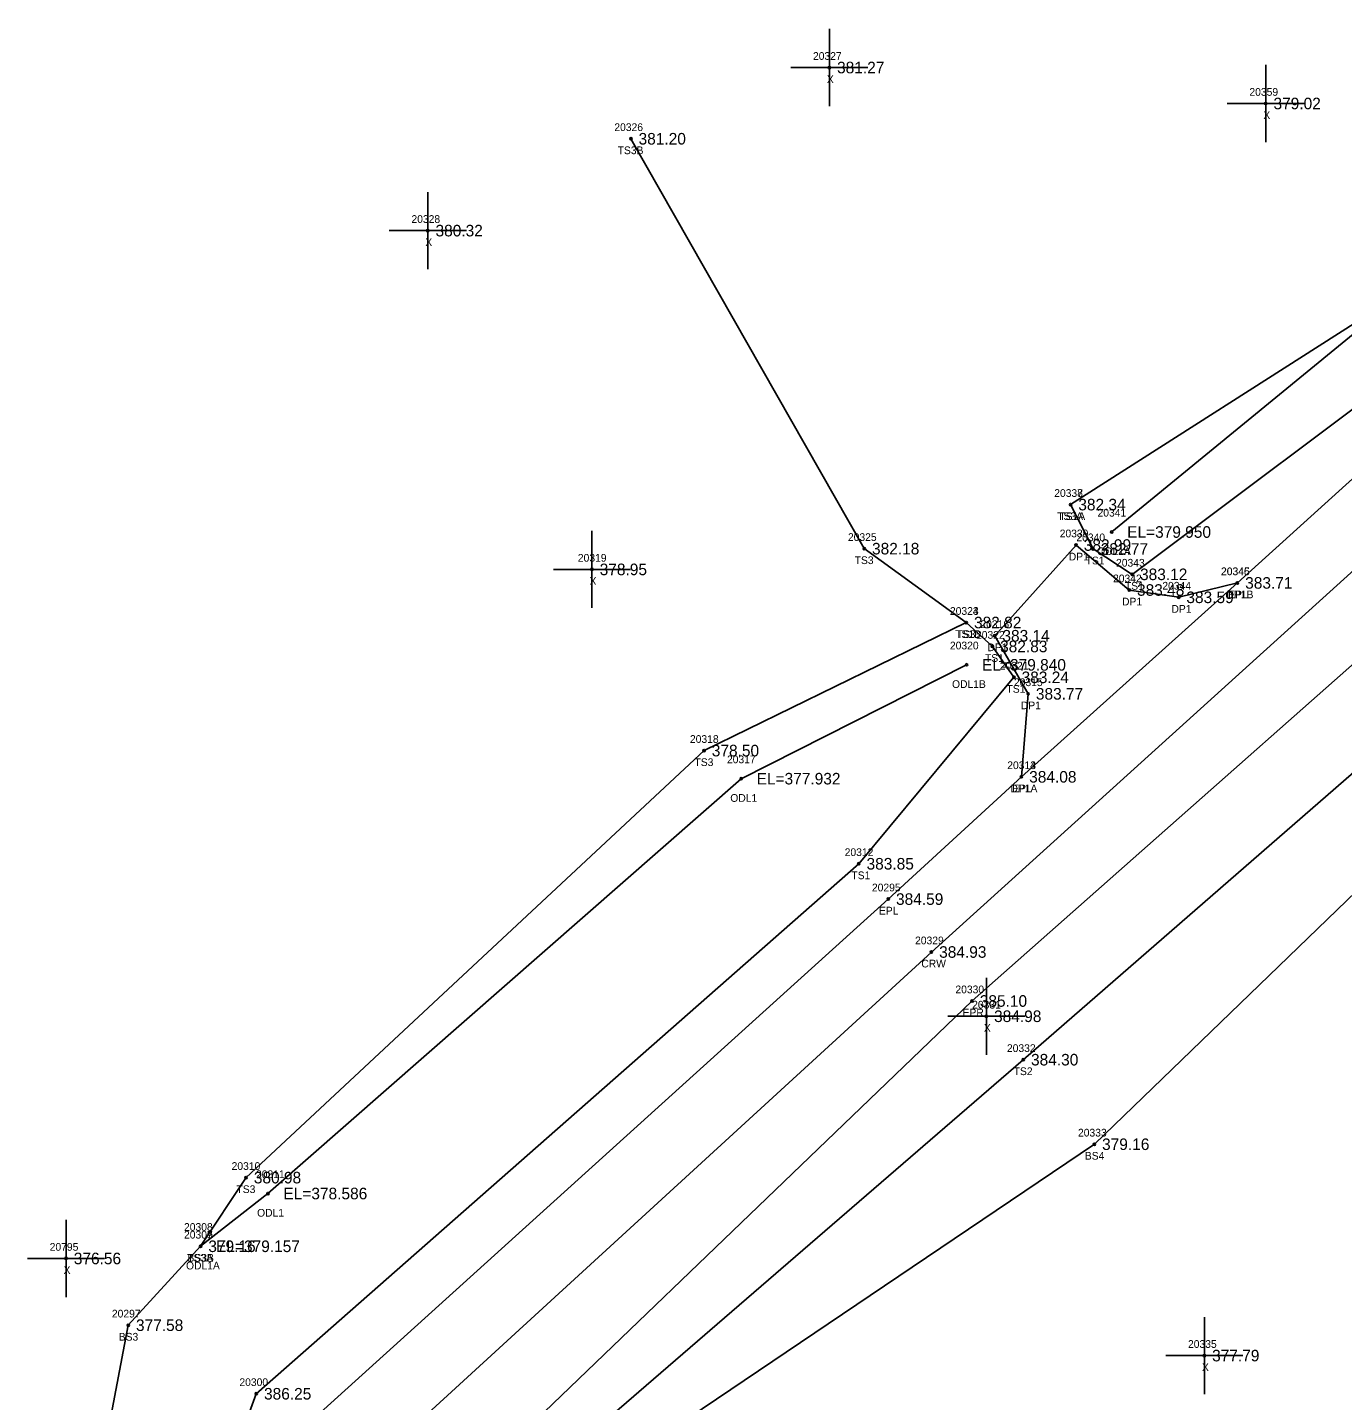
# Model space of a CAD drawing. Extents: x 2116373 to 2118139, y 979529 to 981026.
# Drawn here: x 2117358.2 to 2117528.6, y 980201.2 to 980379.2 of the extents above; entities that cross this region are included whole.
import ezdxf

# ---------------------------------------------------------------- set-up
doc = ezdxf.new("R2010")
doc.units = 0
for name, color, linetype in [('RD_DTM_BkLn1', 7, 'Continuous'), ('RD_DTM_BkLn2', 7, 'Continuous'), ('RD_DTM_BkLn_txCode', 7, 'Continuous'), ('RD_EX_Driveway', 7, 'Continuous'), ('RD_EX_Driveway_txCode', 7, 'Continuous'), ('RD_EX_H2O', 7, 'Continuous'), ('RD_EX_H2O_txCode', 7, 'Continuous'), ('RD_EX_Misc', 7, 'Continuous'), ('RD_EX_Misc_txCode', 7, 'Continuous'), ('RD_EX_Road', 7, 'Continuous'), ('RD_EX_Road_txCode', 7, 'Continuous'), ('RD_EX_TX_Driveway_ELEV', 7, 'Continuous'), ('RD_EX_TX_H2O_ELEV', 7, 'Continuous'), ('RD_EX_TX_Misc_ELEV', 7, 'Continuous'), ('RD_EX_TX_Road_ELEV', 7, 'Continuous'), ('RD_HC_Survey_ELEV', 7, 'Continuous'), ('RD_HC_Survey_txCode', 7, 'Continuous'), ('RD_SMD_Locator', 7, 'Continuous')]:
    doc.layers.add(name, color=color, linetype=linetype)

msp = doc.modelspace()

# ---------------------------------------------------------------- linework, layer by layer
at = {"layer": 'RD_DTM_BkLn1'}
msp.add_lwpolyline([(2117394.63, 980185.41), (2117475.35, 980259.39), (2117549.63, 980326.58), (2117623.5, 980394.2), (2117697.55, 980461.75), (2117735.02, 980495.39), (2117805.43, 980566.78), (2117837.53, 980605.36), (2117867.93, 980645.06), (2117897.09, 980686.34), (2117923.66, 980727.51), (2117948.72, 980771.39), (2117971.22, 980818.34), (2117988.96, 980866.05), (2117991.42, 980873.14), (2118004.26, 980915.09), (2118016.82, 980963.49), (2118028.02, 981013.26)], dxfattribs=at)
at = {"layer": 'RD_DTM_BkLn2'}
msp.add_line((2117493.39, 980317.39), (2117537.18, 980345.39), dxfattribs=at)
for points in [[(2117493.39, 980317.39), (2117496.3, 980311.64), (2117501.39, 980308.35), (2117540.21, 980337.44), (2117614.76, 980403.8), (2117689.51, 980469.61), (2117729.91, 980504.53), (2117761.86, 980538.86), (2117795.32, 980575.41), (2117828.25, 980612.61), (2117859.59, 980651.69), (2117887.1, 980692.35), (2117913.78, 980733.2), (2117937.24, 980777.08), (2117959.23, 980820.82), (2117978.84, 980869.89), (2117994.26, 980920.18), (2118007.51, 980964.57), (2118017.18, 981016.23)], [(2117403.18, 980177.15), (2117405.35, 980174.66), (2117487.26, 980245.43), (2117563.99, 980312.17), (2117634.65, 980381.46), (2117704.3, 980451.46), (2117722.65, 980465.11), (2117743.87, 980484.9), (2117780.03, 980521.07), (2117815.83, 980557.8), (2117846.79, 980597.78), (2117878.62, 980636.27), (2117911.26, 980677.34), (2117934.7, 980720.41), (2117959.82, 980759.29), (2117971.51, 980778.31), (2117986.8, 980774.26), (2117987.85, 980770.9), (2117995.22, 980745.17), (2118001.26, 980694.98), (2118008.4, 980640.04)], [(2117389.45, 980162.29), (2117496.47, 980234.47), (2117570.67, 980306.14), (2117640.42, 980376.1), (2117709.81, 980445.93), (2117716.62, 980450.81)], [(2117380.62, 980221.24), (2117386.52, 980230.14), (2117445.88, 980285.5), (2117479.87, 980302.1), (2117466.65, 980311.68), (2117436.39, 980364.82)], [(2117385.63, 980196.08), (2117387.84, 980202.12), (2117465.94, 980270.83), (2117486.04, 980295), (2117483.25, 980299), (2117479.87, 980302.1)], [(2117365.85, 980182.55), (2117371.24, 980211.01), (2117380.62, 980221.24)]]:
    msp.add_lwpolyline(points, dxfattribs=at)
at = {"layer": 'RD_EX_Driveway'}
msp.add_lwpolyline([(2117487.02, 980282.1), (2117487.89, 980292.86), (2117483.55, 980300.39), (2117494.1, 980312.15), (2117501, 980306.32), (2117507.4, 980305.37), (2117515.02, 980307.24)], dxfattribs=at)
at = {"layer": 'RD_EX_H2O'}
msp.add_line((2117498.72, 980313.84), (2117537.18, 980345.39), dxfattribs=at)
msp.add_lwpolyline([(2117380.62, 980221.24), (2117389.35, 980228.08), (2117450.69, 980281.86), (2117479.91, 980296.62)], dxfattribs=at)
at = {"layer": 'RD_EX_Misc'}
for p, q in [((2117462.12, 980369.05), (2117462.12, 980379.05)), ((2117457.12, 980374.05), (2117467.12, 980374.05)), ((2117518.69, 980364.39), (2117518.69, 980374.39)), ((2117513.69, 980369.39), (2117523.69, 980369.39)), ((2117410.07, 980347.91), (2117410.07, 980357.91)), ((2117405.07, 980352.91), (2117415.07, 980352.91)), ((2117431.35, 980303.99), (2117431.35, 980313.99)), ((2117426.35, 980308.99), (2117436.35, 980308.99)), ((2117482.47, 980246.06), (2117482.47, 980256.06)), ((2117477.47, 980251.06), (2117487.47, 980251.06)), ((2117363.18, 980214.66), (2117363.18, 980224.66)), ((2117358.18, 980219.66), (2117368.18, 980219.66)), ((2117510.73, 980202.07), (2117510.73, 980212.07)), ((2117505.73, 980207.07), (2117515.73, 980207.07))]:
    msp.add_line(p, q, dxfattribs=at)
at = {"layer": 'RD_EX_Road'}
for points in [[(2117394.63, 980185.41), (2117388.45, 980192.75), (2117469.76, 980266.25), (2117487.02, 980282.1), (2117515.02, 980307.24), (2117543.53, 980333.04), (2117617.72, 980400.8), (2117691.88, 980468.07), (2117729.57, 980501.96), (2117798.93, 980572.83), (2117831.02, 980611), (2117861.69, 980650.07), (2117890.37, 980690.61), (2117916.67, 980731.93), (2117941.38, 980774.84), (2117963.75, 980821.95), (2117981.56, 980869.78), (2117996.2, 980917.73), (2118008.9, 980966.42), (2118019.55, 981015.46)], [(2117394.63, 980185.41), (2117401.85, 980177.36), (2117480.62, 980253.04), (2117556.27, 980319.95), (2117629.74, 980387.35), (2117703.2, 980454.29), (2117741.39, 980488.9), (2117777.53, 980523.58), (2117812.39, 980561.12), (2117844.66, 980599.64), (2117874.87, 980639.35), (2117904.78, 980681.4), (2117931.2, 980722.71), (2117957.05, 980767.35), (2117963.67, 980781.11), (2117980.28, 980814.62), (2117994.42, 980851.98)]]:
    msp.add_lwpolyline(points, dxfattribs=at)
at = {"layer": 'RD_SMD_Locator'}
for centre in [(2117462.12, 980374.05), (2117518.69, 980369.39), (2117436.39, 980364.82), (2117410.07, 980352.91), (2117493.39, 980317.39), (2117493.39, 980317.39), (2117498.72, 980313.84), (2117466.65, 980311.68), (2117494.1, 980312.15), (2117496.3, 980311.64), (2117431.35, 980308.99), (2117501.39, 980308.35), (2117515.02, 980307.24), (2117515.02, 980307.24), (2117501, 980306.32), (2117507.4, 980305.37), (2117479.87, 980302.1), (2117479.87, 980302.1), (2117483.55, 980300.39), (2117483.25, 980299), (2117479.91, 980296.62), (2117486.04, 980295), (2117487.89, 980292.86), (2117445.88, 980285.5), (2117450.69, 980281.86), (2117487.02, 980282.1), (2117487.02, 980282.1), (2117465.94, 980270.83), (2117469.76, 980266.25), (2117475.35, 980259.39), (2117480.62, 980253.04), (2117482.47, 980251.06), (2117487.26, 980245.43), (2117496.47, 980234.47), (2117386.52, 980230.14), (2117389.35, 980228.08), (2117380.62, 980221.24), (2117380.62, 980221.24), (2117380.62, 980221.24), (2117363.18, 980219.66), (2117371.24, 980211.01), (2117510.73, 980207.07), (2117387.84, 980202.12)]:
    msp.add_circle(centre, 0.15, dxfattribs=at)

# ---------------------------------------------------------------- texts
at = {"layer": 'RD_DTM_BkLn_txCode'}
for s, p in [('20326', (2117434.25, 980365.82)), ('TS3B', (2117434.68, 980362.82)), ('20337', (2117491.27, 980318.39)), ('20338', (2117491.27, 980318.39)), ('TS3A', (2117491.66, 980315.39)), ('TS1A', (2117491.94, 980315.39)), ('20325', (2117464.53, 980312.68)), ('20340', (2117494.14, 980312.64)), ('TS3', (2117465.4, 980309.68)), ('TS1', (2117495.34, 980309.64)), ('20343', (2117499.28, 980309.35)), ('TS1', (2117500.43, 980306.35)), ('20323', (2117477.75, 980303.1)), ('20324', (2117477.75, 980303.1)), ('TS1B', (2117478.43, 980300.1)), ('TS3', (2117478.62, 980300.1)), ('20322', (2117481.13, 980300)), ('TS1', (2117482.29, 980297)), ('20321', (2117484.21, 980296)), ('TS1', (2117485.08, 980293)), ('20318', (2117444.05, 980286.5)), ('TS3', (2117444.64, 980283.5)), ('20312', (2117464.11, 980271.83)), ('TS1', (2117464.98, 980268.83)), ('20332', (2117485.14, 980246.43)), ('TS2', (2117486.01, 980243.43)), ('20333', (2117494.35, 980235.47)), ('BS4', (2117495.24, 980232.47)), ('20310', (2117384.64, 980231.14)), ('TS3', (2117385.27, 980228.14)), ('20307', (2117378.47, 980222.24)), ('20309', (2117378.47, 980222.24)), ('TS3A', (2117378.89, 980219.24)), ('BS3B', (2117378.92, 980219.24)), ('20297', (2117369.12, 980212.01)), ('BS3', (2117370.01, 980209.01)), ('20300', (2117385.65, 980203.12))]:
    msp.add_text(s, height=1, dxfattribs=at).set_placement(p)
at = {"layer": 'RD_EX_Driveway_txCode'}
for s, p in [('20339', (2117491.98, 980313.15)), ('DP1', (2117493.15, 980310.15)), ('20345', (2117512.9, 980308.24)), ('20342', (2117498.89, 980307.32)), ('20344', (2117505.28, 980306.37)), ('DP1B', (2117513.6, 980305.24)), ('DP1', (2117500.06, 980304.32)), ('DP1', (2117506.46, 980303.37)), ('20316', (2117481.7, 980301.39)), ('DP1', (2117482.61, 980298.39)), ('20315', (2117486.05, 980293.86)), ('DP1', (2117486.94, 980290.86)), ('20314', (2117485.18, 980283.1)), ('DP1A', (2117485.59, 980280.1))]:
    msp.add_text(s, height=1, dxfattribs=at).set_placement(p)
at = {"layer": 'RD_EX_H2O_txCode'}
for s, p in [('20341', (2117496.88, 980315.84)), ('ODL1A', (2117496.82, 980310.84)), ('20320', (2117477.75, 980298.62)), ('ODL1B', (2117478.02, 980293.62)), ('20317', (2117448.85, 980283.86)), ('ODL1', (2117449.28, 980278.86)), ('20311', (2117387.8, 980230.08)), ('ODL1', (2117387.94, 980225.08)), ('20308', (2117378.47, 980223.24)), ('ODL1A', (2117378.73, 980218.24))]:
    msp.add_text(s, height=1, dxfattribs=at).set_placement(p)
at = {"layer": 'RD_EX_Misc_txCode'}
for s, p in [('20327', (2117460, 980375.05)), ('X', (2117461.8, 980372.05)), ('20359', (2117516.57, 980370.39)), ('X', (2117518.38, 980367.39)), ('20328', (2117407.95, 980353.91)), ('X', (2117409.75, 980350.91)), ('20319', (2117429.52, 980309.99)), ('X', (2117431.04, 980306.99)), ('20331', (2117480.63, 980252.06)), ('X', (2117482.15, 980249.06)), ('20795', (2117361.06, 980220.66)), ('X', (2117362.86, 980217.66)), ('20335', (2117508.61, 980208.07)), ('X', (2117510.42, 980205.07))]:
    msp.add_text(s, height=1, dxfattribs=at).set_placement(p)
at = {"layer": 'RD_EX_Road_txCode'}
for s, p in [('20346', (2117512.88, 980308.24)), ('EPL', (2117513.82, 980305.24)), ('20313', (2117485.18, 980283.1)), ('EPL', (2117485.81, 980280.1)), ('20295', (2117467.64, 980267.25)), ('EPL', (2117468.55, 980264.25)), ('20330', (2117478.46, 980254.04)), ('EPR', (2117479.39, 980251.04))]:
    msp.add_text(s, height=1, dxfattribs=at).set_placement(p)
at = {"layer": 'RD_EX_TX_Driveway_ELEV'}
for s, p in [('382.99', (2117495.1, 980311.4)), ('383.71', (2117516.02, 980306.49)), ('383.48', (2117502, 980305.57)), ('383.59', (2117508.4, 980304.62)), ('383.14', (2117484.55, 980299.64)), ('383.77', (2117488.89, 980292.11)), ('384.08', (2117488.02, 980281.35))]:
    msp.add_text(s, height=1.5, dxfattribs=at).set_placement(p)
at = {"layer": 'RD_EX_TX_H2O_ELEV'}
for s, p in [('EL=379.950', (2117500.72, 980313.09)), ('EL=379.840', (2117481.91, 980295.87)), ('EL=377.932', (2117452.69, 980281.11)), ('EL=378.586', (2117391.35, 980227.33)), ('EL=379.157', (2117382.62, 980220.49))]:
    msp.add_text(s, height=1.5, dxfattribs=at).set_placement(p)
at = {"layer": 'RD_EX_TX_Misc_ELEV'}
for s, p in [('381.27', (2117463.12, 980373.3)), ('379.02', (2117519.69, 980368.64)), ('381.20', (2117437.39, 980364.07)), ('380.32', (2117411.07, 980352.16)), ('382.34', (2117494.39, 980316.64)), ('382.34', (2117494.39, 980316.64)), ('382.18', (2117467.65, 980310.93)), ('382.77', (2117497.3, 980310.89)), ('378.95', (2117432.35, 980308.24)), ('383.12', (2117502.39, 980307.6)), ('382.82', (2117480.87, 980301.35)), ('382.82', (2117480.87, 980301.35)), ('382.83', (2117484.25, 980298.25)), ('383.24', (2117487.04, 980294.25)), ('378.50', (2117446.88, 980284.75)), ('383.85', (2117466.94, 980270.08)), ('384.98', (2117483.47, 980250.31)), ('384.30', (2117488.26, 980244.68)), ('379.16', (2117497.47, 980233.72)), ('380.98', (2117387.52, 980229.39)), ('379.16', (2117381.62, 980220.49)), ('379.16', (2117381.62, 980220.49)), ('376.56', (2117364.18, 980218.91)), ('377.58', (2117372.24, 980210.26)), ('377.79', (2117511.73, 980206.32)), ('386.25', (2117388.84, 980201.37))]:
    msp.add_text(s, height=1.5, dxfattribs=at).set_placement(p)
at = {"layer": 'RD_EX_TX_Road_ELEV'}
for s, p in [('383.71', (2117516.02, 980306.49)), ('384.08', (2117488.02, 980281.35)), ('384.59', (2117470.76, 980265.5)), ('385.10', (2117481.62, 980252.29))]:
    msp.add_text(s, height=1.5, dxfattribs=at).set_placement(p)
at = {"layer": 'RD_HC_Survey_ELEV'}
msp.add_text('384.93', height=1.5, dxfattribs=at).set_placement((2117476.35, 980258.64))
at = {"layer": 'RD_HC_Survey_txCode'}
for s, p in [('20329', (2117473.23, 980260.39)), ('CRW', (2117474.04, 980257.39))]:
    msp.add_text(s, height=1, dxfattribs=at).set_placement(p)

doc.saveas('drawing.dxf')
